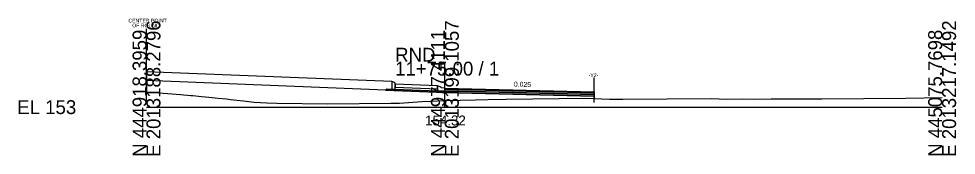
# Model space of a CAD drawing. Extents: x -26 to 163, y -10 to 7518.
# Drawn here: x -25.7 to 162.8, y 3490.3 to 3517.8 of the extents above; entities that cross this region are included whole.
import ezdxf

# ---------------------------------------------------------------- set-up
doc = ezdxf.new("R2010")
doc.units = 0
for name, color, linetype in [('Exist Cross Section Cell', 7, 'Continuous'), ('Exist XS Center Line Elevation Label', 7, 'Continuous'), ('Exist XS Ground Line', 7, 'Continuous'), ('Prop CMT Conc Surface', 7, 'Continuous'), ('Prop CMT Concrete Structures', 7, 'Continuous'), ('Prop CMT Pvmt Course 1', 7, 'Continuous'), ('Prop CMT Pvmt Course 1 CG', 7, 'Continuous'), ('Prop CMT Pvmt Course 2', 7, 'Continuous'), ('Prop CMT Pvmt Course 3', 7, 'Continuous'), ('Prop CMT Pvmt Surface', 7, 'Continuous'), ('Prop CMT Shear Line', 7, 'Continuous'), ('Prop CMT Shear Line Text', 7, 'Continuous'), ('Prop CMT Slope Grass', 7, 'Continuous'), ('Prop CMT Subgrade Earthwork', 7, 'Continuous'), ('Prop XS Earthwork Shape', 7, 'Continuous'), ('Prop XS SE Text', 7, 'Continuous')]:
    doc.layers.add(name, color=color, linetype=linetype)

msp = doc.modelspace()

# ---------------------------------------------------------------- linework, layer by layer
at = {"layer": 'Exist Cross Section Cell'}
for p, q in [((60, 3500), (60, 3509.16)), ((0, 3500), (60, 3500)), ((60, 3500), (160, 3500))]:
    msp.add_line(p, q, dxfattribs=at)
at = {"layer": 'Exist XS Ground Line'}
msp.add_lwpolyline([(0, 3503.05), (0.36, 3503.03), (1.71, 3502.96), (2.51, 3502.9), (4.25, 3502.78), (6.86, 3502.58), (8.94, 3502.37), (9.31, 3502.33), (11.08, 3502.17), (11.84, 3502.1), (13.22, 3501.95), (14.38, 3501.84), (16.06, 3501.65), (16.92, 3501.56), (19.52, 3501.26), (20.01, 3501.2), (20.55, 3501.13), (21.64, 3500.99), (24.21, 3500.88), (26.18, 3500.82), (36.49, 3500.65), (49.12, 3500.78), (49.94, 3500.79), (50.86, 3500.81), (55.34, 3501.14), (57.13, 3501.23), (60, 3501.32), (66.14, 3501.5), (68.68, 3501.56), (72.33, 3501.63), (88.33, 3501.79), (93.1, 3501.64), (95.79, 3501.61), (113.59, 3501.73), (116.69, 3501.62), (119.89, 3501.7), (122.3, 3501.64), (125.65, 3501.66), (132.53, 3501.69), (135.82, 3501.7), (152.68, 3501.84), (160, 3501.96)], dxfattribs=at)
at = {"layer": 'Prop CMT Conc Surface'}
for points in [[(50, 3504.83), (49.96, 3504.93), (49.85, 3504.97), (49.34, 3505.16)], [(50, 3504.66), (50, 3504.83)], [(60, 3503.86), (59.25, 3503.88), (59.25, 3504.05), (58.5, 3504.3)]]:
    msp.add_lwpolyline(points, dxfattribs=at)
at = {"layer": 'Prop CMT Concrete Structures'}
for points in [[(50, 3504.83), (49.96, 3504.93), (49.85, 3504.97), (49.34, 3505.16)], [(49.34, 3505.16), (49.34, 3503.66)], [(50, 3504.66), (50, 3504.83)], [(49.34, 3503.66), (50, 3503.66)], [(50, 3503.66), (50, 3504.66)], [(50, 3504.66), (50, 3504.08)], [(58.5, 3504.3), (50, 3504.64)], [(50, 3504.06), (58.5, 3503.72)], [(60, 3503.86), (59.25, 3503.88), (59.25, 3504.05), (58.5, 3504.3)], [(58.5, 3504.3), (58.5, 3503.32)], [(58.5, 3503.72), (58.5, 3504.3)], [(58.5, 3503.32), (60, 3503.28)], [(60, 3503.28), (60, 3503.86)]]:
    msp.add_lwpolyline(points, dxfattribs=at)
at = {"layer": 'Prop CMT Pvmt Course 1'}
for points in [[(60, 3503.86), (90, 3503.11)], [(60, 3503.61), (60, 3503.86)], [(90, 3502.86), (60, 3503.61)], [(90, 3503.11), (90, 3502.86)]]:
    msp.add_lwpolyline(points, dxfattribs=at)
msp.add_lwpolyline([(60, 3503.61), (60, 3503.74), (60, 3503.74), (60, 3503.61)], close=True, dxfattribs=at)
at = {"layer": 'Prop CMT Pvmt Course 1 CG'}
for points in [[(60, 3502.95), (60, 3503.28)], [(90, 3502.19), (90, 3502.53)]]:
    msp.add_lwpolyline(points, dxfattribs=at)
at = {"layer": 'Prop CMT Pvmt Course 2'}
for points in [[(60, 3503.28), (60, 3503.61)], [(60, 3503.61), (90, 3502.86)], [(90, 3502.53), (60, 3503.28)], [(90, 3502.86), (90, 3502.53)]]:
    msp.add_lwpolyline(points, dxfattribs=at)
at = {"layer": 'Prop CMT Pvmt Course 3'}
for points in [[(50, 3503.66), (58.5, 3503.32)], [(60, 3503.28), (90, 3502.53)], [(60, 3502.95), (60, 3503.28)], [(90, 3502.19), (60, 3502.95)], [(90, 3502.53), (90, 3502.19)]]:
    msp.add_lwpolyline(points, dxfattribs=at)
at = {"layer": 'Prop CMT Pvmt Surface'}
msp.add_lwpolyline([(60, 3503.86), (90, 3503.11)], dxfattribs=at)
at = {"layer": 'Prop CMT Shear Line'}
for p, q in [((0, 3500.8), (0, 3515.8)), ((90, 3500.94), (90, 3505.95))]:
    msp.add_line(p, q, dxfattribs=at)
at = {"layer": 'Prop CMT Slope Grass'}
for p, q in [((49.34, 3505.14), (0, 3507.11)), ((48.06, 3503.43), (0, 3505.35))]:
    msp.add_line(p, q, dxfattribs=at)
at = {"layer": 'Prop CMT Subgrade Earthwork'}
for p, q in [((0, 3507.11), (0, 3503.05)), ((48.34, 3503.7), (48.06, 3503.43)), ((90, 3503.11), (90, 3502.19)), ((90, 3502.19), (90, 3501.74))]:
    msp.add_line(p, q, dxfattribs=at)
for points in [[(48.06, 3503.43), (60, 3502.95)], [(48.34, 3503.7), (49.34, 3503.66)], [(60, 3502.95), (90, 3502.19)]]:
    msp.add_lwpolyline(points, dxfattribs=at)
at = {"layer": 'Prop XS Earthwork Shape'}
msp.add_lwpolyline([(0, 3505.35), (0, 3503.05), (0.36, 3503.03), (1.71, 3502.96), (2.51, 3502.9), (4.25, 3502.78), (6.86, 3502.58), (8.94, 3502.37), (9.31, 3502.33), (11.08, 3502.17), (11.84, 3502.1), (13.22, 3501.95), (14.38, 3501.84), (16.06, 3501.65), (16.92, 3501.56), (19.52, 3501.26), (20.01, 3501.2), (20.55, 3501.13), (21.64, 3500.99), (24.21, 3500.88), (26.18, 3500.82), (36.49, 3500.65), (49.12, 3500.78), (49.94, 3500.79), (50.86, 3500.81), (55.34, 3501.14), (57.13, 3501.23), (60, 3501.32), (66.14, 3501.5), (68.68, 3501.56), (72.33, 3501.63), (88.33, 3501.79), (90, 3501.74), (90, 3502.19), (60, 3502.95), (48.06, 3503.43)], close=True, dxfattribs=at)

# ---------------------------------------------------------------- texts
at = {"layer": 'Exist Cross Section Cell'}
for s, p in [('E 2013188.2796', (2.8, 3490)), ('E 2013199.1057', (62.8, 3490)), ('E 2013217.1492', (162.8, 3490)), ('N 444918.3959', (0, 3490)), ('N 444977.4111', (60, 3490)), ('N 445075.7698', (160, 3490))]:
    msp.add_text(s, height=2.8, rotation=90, dxfattribs=at).set_placement(p)
for s, p in [('RND', (50, 3509.16)), ('11+75.00 / 1', (50, 3506.36)), ('EL 153', (-26, 3498.6))]:
    msp.add_text(s, height=2.8, dxfattribs=at).set_placement(p)
at = {"layer": 'Exist XS Center Line Elevation Label'}
msp.add_text('154.32', height=2, dxfattribs=at).set_placement((56.03, 3496.32))
at = {"layer": 'Prop CMT Shear Line Text'}
for s, p in [('CENTER POINT', (-3.64, 3517.06)), ('OF ROUND', (-2.88, 3516.08)), ('-Y2-', (88.91, 3506.06))]:
    msp.add_text(s, height=0.75, dxfattribs=at).set_placement(p)
at = {"layer": 'Prop XS SE Text'}
msp.add_text('0.025', height=1, rotation=358.5613, dxfattribs=at).set_placement((73.87, 3504.14))

doc.saveas('drawing.dxf')
